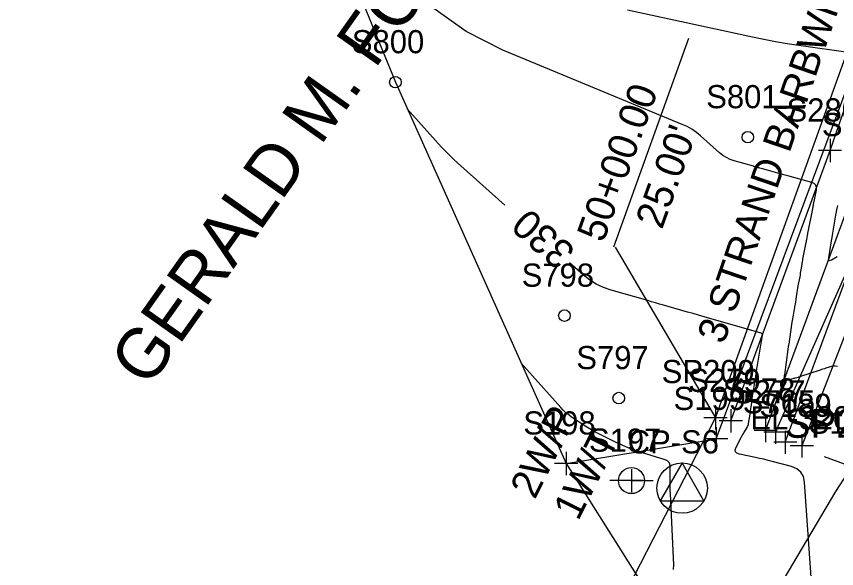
# Model space of a CAD drawing. Extents: x 816928 to 825690, y 436959 to 448212.
# Drawn here: x 818545.2 to 818686.8, y 444502.7 to 444598.1 of the extents above; entities that cross this region are included whole.
import ezdxf

# ---------------------------------------------------------------- set-up
doc = ezdxf.new("R2010")
doc.units = 0
for name, color, linetype in [('DESIGN - SCRATCH - User 1', 7, 'Continuous'), ('SURVEY - CENTERLINE - Preliminary - Development', 7, 'Continuous'), ('SURVEY - CENTERLINE - Preliminary Text', 7, 'Continuous'), ('SURVEY - CONTOURS - Index with Text', 7, 'Continuous'), ('SURVEY - CONTOURS - Intermediate with optional Text', 7, 'Continuous'), ('SURVEY - CONTROL with Text', 7, 'Continuous'), ('SURVEY - DRAINAGE - Area Shapes', 7, 'Continuous'), ('SURVEY - DTM - Breaklines', 7, 'Continuous'), ('SURVEY - DTM - Breaklines - Points - Locators', 7, 'Continuous'), ('SURVEY - DTM - Breaklines - Points - Numbers', 7, 'Continuous'), ('SURVEY - DTM - Spot Points - Locators', 7, 'Continuous'), ('SURVEY - DTM - Spot Points - Point Numbers', 7, 'Continuous'), ('SURVEY - NON-TRANSPORTATION - Features', 7, 'Continuous'), ('SURVEY - NON-TRANSPORTATION - Features - Points - Locators', 7, 'Continuous'), ('SURVEY - NON-TRANSPORTATION - Features - Points - Numbers', 7, 'Continuous'), ('SURVEY - NON-TRANSPORTATION - Features Text', 7, 'Continuous'), ('SURVEY - PROPERTY - Owners', 7, 'Continuous'), ('SURVEY - PROPERTY - Parcels', 7, 'Continuous'), ('SURVEY - PROPERTY - ROW Lines', 7, 'Continuous'), ('SURVEY - PROPERTY - ROW Lines - Points - Elevations', 7, 'Continuous'), ('SURVEY - PROPERTY - ROW Lines - Points - Locators', 7, 'Continuous'), ('SURVEY - PROPERTY - ROW Lines - Points - Numbers', 7, 'Continuous'), ('SURVEY - PROPERTY - Station and Offset Flags', 7, 'Continuous'), ('SURVEY - TRANSPORTATION - Roads', 7, 'Continuous'), ('SURVEY - TRANSPORTATION - Roads - Points - Locators', 7, 'Continuous'), ('SURVEY - TRANSPORTATION - Roads - Points - Numbers', 7, 'Continuous'), ('SURVEY - UTILITIES - Gas - Points - Locators', 7, 'Continuous'), ('SURVEY - UTILITIES - Gas - Points - Numbers', 7, 'Continuous'), ('SURVEY - UTILITIES - Gas with Text', 7, 'Continuous'), ('SURVEY - UTILITIES - Poles and Miscellaneous - Points - Locators', 7, 'Continuous'), ('SURVEY - UTILITIES - Poles and Miscellaneous - Points - Numbers', 7, 'Continuous'), ('SURVEY - UTILITIES - Poles and Miscellaneous with Text', 7, 'Continuous')]:
    doc.layers.add(name, color=color, linetype=linetype)

msp = doc.modelspace()

# ---------------------------------------------------------------- linework, layer by layer
at = {"layer": 'DESIGN - SCRATCH - User 1'}
msp.add_lwpolyline([(818705.72, 444876.51), (818677.89, 444822.37), (818647.85, 444766.47), (818627.5, 444720.97), (818604.18, 444676.53), (818583.87, 444652.29), (818610.67, 444586.77), (818640.15, 444520.89), (818676.04, 444463.99)], dxfattribs=at)
at = {"layer": 'SURVEY - CENTERLINE - Preliminary Text'}
msp.add_line((818689.48, 444520.32), (818684.77, 444522.01), dxfattribs=at)
at = {"layer": 'SURVEY - CONTOURS - Index with Text'}
for points in [[(818629.55, 444565.54), (818621.98, 444572.29), (818620.82, 444573.35), (818619.71, 444574.44), (818618.62, 444575.56), (818617.57, 444576.71), (818612.72, 444582.17)], [(818682.87, 444495.45), (818681.3, 444517.68), (818681.11, 444518.65), (818680.68, 444519.41), (818680, 444519.98), (818679.09, 444520.35), (818675.73, 444521.24), (818675.01, 444521.42), (818674.28, 444521.6), (818673.55, 444521.76), (818672.83, 444521.92), (818670.06, 444522.5), (818669.62, 444522.66), (818669.39, 444522.9), (818669.35, 444523.25), (818669.5, 444523.68), (818670.44, 444525.46), (818670.56, 444525.69), (818670.69, 444525.92), (818670.82, 444526.15), (818670.96, 444526.37), (818671.4, 444527.11), (818671.49, 444527.27), (818671.56, 444527.43), (818671.61, 444527.61), (818671.65, 444527.79), (818671.96, 444529.74), (818672.01, 444530.04), (818672.05, 444530.35), (818672.09, 444530.65), (818672.13, 444530.96), (818672.25, 444531.95), (818672.28, 444532.17), (818672.3, 444532.38), (818672.34, 444532.59), (818672.37, 444532.8), (818672.89, 444535.94), (818672.92, 444536.1), (818672.94, 444536.26), (818672.96, 444536.42), (818672.98, 444536.58), (818673.05, 444537.1), (818673.06, 444537.21), (818673.08, 444537.32), (818673.1, 444537.43), (818673.12, 444537.54), (818673.89, 444542.01), (818673.89, 444542.04), (818673.9, 444542.07), (818673.9, 444542.09), (818673.91, 444542.12), (818673.92, 444542.21), (818673.92, 444542.23), (818673.92, 444542.24), (818673.93, 444542.26), (818673.93, 444542.28), (818674.06, 444542.99), (818674.06, 444543.13), (818674.02, 444543.24), (818673.94, 444543.33), (818673.81, 444543.38), (818664, 444546.21), (818663.03, 444546.49), (818662.06, 444546.77), (818661.09, 444547.05), (818660.12, 444547.33), (818656.95, 444548.24), (818656.27, 444548.44), (818655.59, 444548.64), (818654.91, 444548.83), (818654.23, 444549.02), (818647.9, 444550.84), (818646.58, 444551.29), (818645.33, 444551.89), (818644.17, 444552.62), (818643.07, 444553.49), (818640.75, 444555.56)]]:
    msp.add_lwpolyline(points, dxfattribs=at)
at = {"layer": 'SURVEY - CONTOURS - Intermediate with optional Text'}
for points in [[(818687.03, 444537.65), (818686.61, 444537.69), (818686.56, 444537.7), (818686.52, 444537.7), (818686.47, 444537.71), (818686.42, 444537.71), (818686.27, 444537.73), (818686.24, 444537.73), (818686.21, 444537.73), (818686.18, 444537.73), (818686.15, 444537.72), (818684.99, 444537.34), (818684.74, 444537.26), (818684.49, 444537.18), (818684.24, 444537.1), (818683.99, 444537.01), (818680.64, 444535.91), (818680.6, 444535.89), (818680.56, 444535.88), (818680.52, 444535.86), (818680.48, 444535.85), (818680.35, 444535.79), (818680.33, 444535.78), (818680.3, 444535.77), (818680.27, 444535.77), (818680.24, 444535.76), (818679.73, 444535.64), (818679.62, 444535.61), (818679.52, 444535.58), (818679.41, 444535.55), (818679.3, 444535.52), (818678.17, 444535.21), (818678.13, 444535.19), (818678.08, 444535.19), (818678.03, 444535.18), (818677.98, 444535.17), (818677.82, 444535.17), (818677.79, 444535.17), (818677.77, 444535.18), (818677.76, 444535.2), (818677.76, 444535.23), (818677.85, 444535.94), (818677.85, 444535.96), (818677.86, 444535.99), (818677.86, 444536.02), (818677.87, 444536.04), (818677.88, 444536.13), (818677.88, 444536.14), (818677.89, 444536.16), (818677.89, 444536.18), (818677.89, 444536.2), (818678.49, 444540.6), (818678.51, 444540.78), (818678.54, 444540.95), (818678.57, 444541.13), (818678.6, 444541.3), (818678.7, 444541.87), (818678.72, 444541.99), (818678.74, 444542.11), (818678.76, 444542.24), (818678.78, 444542.36), (818679.19, 444545.28), (818679.24, 444545.59), (818679.29, 444545.9), (818679.34, 444546.21), (818679.4, 444546.52), (818679.59, 444547.53), (818679.63, 444547.75), (818679.66, 444547.97), (818679.7, 444548.19), (818679.73, 444548.41), (818679.99, 444550.11), (818680.04, 444550.47), (818680.1, 444550.83), (818680.17, 444551.2), (818680.23, 444551.56), (818680.53, 444553.14), (818680.59, 444553.44), (818680.64, 444553.74), (818680.69, 444554.04), (818680.74, 444554.34), (818680.9, 444555.33), (818680.93, 444555.54), (818680.97, 444555.75), (818681, 444555.96), (818681.04, 444556.17), (818681.61, 444559.06), (818681.65, 444559.25), (818681.68, 444559.43), (818681.71, 444559.61), (818681.74, 444559.8), (818681.84, 444560.4), (818681.86, 444560.53), (818681.88, 444560.66), (818681.91, 444560.79), (818681.93, 444560.92), (818682.73, 444564.9), (818682.75, 444564.98), (818682.76, 444565.05), (818682.78, 444565.13), (818682.79, 444565.2), (818682.83, 444565.45), (818682.84, 444565.5), (818682.85, 444565.56), (818682.86, 444565.61), (818682.87, 444565.66), (818683.37, 444568.1), (818683.4, 444568.57), (818683.27, 444568.95), (818682.99, 444569.24), (818682.56, 444569.43), (818678.4, 444570.59), (818677.97, 444570.71), (818677.54, 444570.83), (818677.11, 444570.95), (818676.68, 444571.07), (818675.07, 444571.52), (818674.87, 444571.57), (818674.68, 444571.63), (818674.48, 444571.68), (818674.29, 444571.73), (818673.6, 444571.93), (818673.49, 444571.96), (818673.38, 444571.99), (818673.27, 444572.02), (818673.16, 444572.05), (818672.8, 444572.15), (818672.72, 444572.17), (818672.64, 444572.19), (818672.57, 444572.22), (818672.49, 444572.24), (818669.17, 444573.19), (818668.48, 444573.43), (818667.83, 444573.74), (818667.22, 444574.12), (818666.65, 444574.58), (818663.36, 444577.51), (818662.64, 444578.1), (818661.87, 444578.63), (818661.06, 444579.09), (818660.21, 444579.48), (818629.22, 444592.33), (818622.92, 444595.5), (818617.31, 444599.48)], [(818650.72, 444599.3), (818672.3, 444594.61), (818674.29, 444594.19), (818676.29, 444593.81), (818678.3, 444593.47), (818680.32, 444593.16), (818689.22, 444591.87)], [(818686.99, 444565.44), (818686.85, 444564.73), (818686.81, 444564.58), (818686.79, 444564.43), (818686.76, 444564.27), (818686.73, 444564.12), (818686.1, 444560.35), (818686.08, 444560.25), (818686.06, 444560.15), (818686.05, 444560.06), (818686.03, 444559.96), (818685.96, 444559.64), (818685.95, 444559.57), (818685.94, 444559.5), (818685.92, 444559.43), (818685.91, 444559.37), (818685.44, 444556.43), (818685.43, 444556.14), (818685.51, 444555.99), (818685.68, 444555.97), (818685.94, 444556.08), (818686.95, 444556.66)], [(818658.71, 444502.58), (818658.76, 444503.38), (818658.16, 444515.64), (818658.14, 444516.29), (818658.12, 444516.93), (818658.11, 444517.57), (818658.11, 444518.22), (818658.13, 444520.32), (818658.08, 444520.74), (818657.92, 444521.07), (818657.65, 444521.32), (818657.27, 444521.5), (818652.44, 444523.03), (818651.51, 444523.34), (818650.59, 444523.69), (818649.69, 444524.08), (818648.8, 444524.5), (818645.93, 444525.93), (818645.32, 444526.25), (818644.72, 444526.58), (818644.13, 444526.93), (818643.55, 444527.3), (818641.1, 444528.9), (818640.59, 444529.26), (818640.1, 444529.65), (818639.65, 444530.07), (818639.22, 444530.53), (818632.39, 444538.23)]]:
    msp.add_lwpolyline(points, dxfattribs=at)
at = {"layer": 'SURVEY - CONTROL with Text'}
for p, q in [((818660.18, 444520.97), (818656.41, 444514.45)), ((818663.94, 444514.45), (818660.18, 444520.97)), ((818660.18, 444516.62), (818660.18, 444516.62)), ((818656.41, 444514.45), (818663.94, 444514.45))]:
    msp.add_line(p, q, dxfattribs=at)
msp.add_circle((818660.18, 444516.62), 4.35, dxfattribs=at)
at = {"layer": 'SURVEY - DRAINAGE - Area Shapes'}
msp.add_line((818686.72, 444516.06), (818689.48, 444520.32), dxfattribs=at)
msp.add_lwpolyline([(817903.8, 442541.98), (818070.27, 442887.73), (818031.86, 443297.51), (818262.36, 443809.74), (818428.83, 443989.01), (818556.89, 444296.35), (818686.72, 444516.06)], dxfattribs=at)
at = {"layer": 'SURVEY - DTM - Breaklines'}
for points in [[(818668.59, 444528.25), (818685.72, 444574.97), (818701.79, 444621.45), (818719.06, 444668.19), (818736.24, 444715.25), (818753.95, 444762.85), (818774.46, 444810.97), (818792.45, 444864.45), (818805.63, 444902.92), (818824.67, 444952.98), (818842.7, 444999.99), (818860.04, 445043.66), (818874.78, 445092.7), (818880.83, 445100.46), (818882.71, 445127.32), (818888.7, 445139.72), (818911.77, 445177.18)], [(818674.6, 444526.59), (818691.48, 444572.45), (818707.88, 444620.16), (818723.91, 444667.23), (818740.64, 444713.78), (818759.18, 444760.75), (818780.01, 444808.95), (818796, 444863.51), (818810.8, 444901.84), (818829.91, 444950.6), (818849.2, 444995.99), (818867.15, 445042.08), (818885.66, 445087.7), (818887.91, 445097.82), (818891.19, 445123.69), (818896.18, 445136.06), (818917.38, 445175.79)], [(818676.31, 444526.27), (818695.98, 444570.72), (818712.39, 444618.98), (818728.83, 444665.29), (818745.89, 444712.28), (818764.81, 444759.05), (818784.52, 444806.67), (818801.14, 444861.81), (818818.98, 444900.09), (818838.24, 444946.22), (818855.87, 444992.17), (818873.7, 445038.58), (818892.29, 445085.58), (818894.59, 445096.56), (818896.48, 445123.31), (818901.19, 445133.75), (818919.53, 445174.23), (818947.17, 445168.06)]]:
    msp.add_lwpolyline(points, dxfattribs=at)
at = {"layer": 'SURVEY - DTM - Breaklines - Points - Locators'}
for p, q in [((818685.72, 444576.97), (818685.72, 444572.97)), ((818687.72, 444574.97), (818683.72, 444574.97)), ((818668.59, 444530.25), (818668.59, 444526.25)), ((818670.59, 444528.25), (818666.59, 444528.25)), ((818674.6, 444528.59), (818674.6, 444524.59)), ((818676.31, 444528.27), (818676.31, 444524.27)), ((818676.6, 444526.59), (818672.6, 444526.59)), ((818678.31, 444526.27), (818674.31, 444526.27))]:
    msp.add_line(p, q, dxfattribs=at)
at = {"layer": 'SURVEY - DTM - Spot Points - Locators'}
for centre in [(818610.67, 444586.77), (818671.52, 444577.27), (818639.86, 444546.43), (818649.24, 444532.18)]:
    msp.add_circle(centre, 1, dxfattribs=at)
at = {"layer": 'SURVEY - NON-TRANSPORTATION - Features'}
msp.add_lwpolyline([(818640.15, 444520.89), (818666.05, 444525.13), (818695.51, 444604.3), (818745.61, 444742.32), (818768.23, 444804.49), (818806.14, 444902.96), (818848.51, 445015.37), (818878.72, 445102.03)], dxfattribs=at)
at = {"layer": 'SURVEY - NON-TRANSPORTATION - Features - Points - Locators'}
for p, q in [((818666.05, 444527.13), (818666.05, 444523.13)), ((818668.05, 444525.13), (818664.05, 444525.13)), ((818640.15, 444522.89), (818640.15, 444518.89)), ((818642.15, 444520.89), (818638.15, 444520.89))]:
    msp.add_line(p, q, dxfattribs=at)
at = {"layer": 'SURVEY - PROPERTY - Parcels'}
for p, q in [((818665.95, 444528.77), (818717.18, 444671.42)), ((818570.54, 444343.53), (818665.95, 444528.77))]:
    msp.add_line(p, q, dxfattribs=at)
at = {"layer": 'SURVEY - PROPERTY - ROW Lines'}
for p, q in [((818665.95, 444528.77), (818717.18, 444671.42)), ((818570.54, 444343.53), (818665.95, 444528.77))]:
    msp.add_line(p, q, dxfattribs=at)
at = {"layer": 'SURVEY - PROPERTY - ROW Lines - Points - Locators'}
for p, q in [((818665.95, 444530.77), (818665.95, 444526.77)), ((818667.95, 444528.77), (818663.95, 444528.77))]:
    msp.add_line(p, q, dxfattribs=at)
at = {"layer": 'SURVEY - PROPERTY - Station and Offset Flags'}
msp.add_line((818661.29, 444594.3), (818648.35, 444558.26), dxfattribs=at)
msp.add_lwpolyline([(818648.6, 444558.26), (818665.95, 444528.77)], dxfattribs=at)
at = {"layer": 'SURVEY - TRANSPORTATION - Roads'}
msp.add_lwpolyline([(818965.23, 445155.36), (818951.41, 445165.35), (818926.02, 445127.5), (818900.33, 445082.5), (818878.31, 445036.45), (818858.82, 444990.15), (818840.56, 444944.19), (818822.72, 444897.89), (818804.42, 444851.44), (818785.95, 444804.73), (818767.42, 444758.09), (818749.48, 444712.19), (818731.94, 444664.32), (818715.46, 444617.82), (818698.91, 444570.49), (818680.86, 444523.94)], dxfattribs=at)
at = {"layer": 'SURVEY - TRANSPORTATION - Roads - Points - Locators'}
for p, q in [((818680.86, 444525.94), (818680.86, 444521.94)), ((818682.86, 444523.94), (818678.86, 444523.94))]:
    msp.add_line(p, q, dxfattribs=at)
at = {"layer": 'SURVEY - UTILITIES - Gas - Points - Locators'}
for p, q in [((818677.99, 444526.55), (818677.99, 444522.55)), ((818679.99, 444524.55), (818675.99, 444524.55))]:
    msp.add_line(p, q, dxfattribs=at)
at = {"layer": 'SURVEY - UTILITIES - Gas with Text'}
msp.add_lwpolyline([(818677.99, 444524.55), (818704.19, 444595.26), (818729, 444664.07), (818764.63, 444758.42), (818803.58, 444855.27), (818837.4, 444944.84), (818872.36, 445029.49), (818905.91, 445098), (818946.07, 445164.69)], dxfattribs=at)
at = {"layer": 'SURVEY - UTILITIES - Poles and Miscellaneous - Points - Locators'}
for p, q in [((818651.44, 444519.92), (818651.44, 444515.92)), ((818653.44, 444517.92), (818649.44, 444517.92))]:
    msp.add_line(p, q, dxfattribs=at)
at = {"layer": 'SURVEY - UTILITIES - Poles and Miscellaneous with Text'}
for q in [(818647.69, 444517.92), (818655.19, 444517.92)]:
    msp.add_line((818651.44, 444517.92), q, dxfattribs=at)
msp.add_circle((818651.44, 444517.92), 2.25, dxfattribs=at)

# ---------------------------------------------------------------- texts
at = {"layer": 'SURVEY - CENTERLINE - Preliminary - Development'}
msp.add_text('SP204', height=5, dxfattribs=at).set_placement((818677.87, 444525.32))
at = {"layer": 'SURVEY - CONTOURS - Index with Text'}
msp.add_text('330', height=5, rotation=138.3011, dxfattribs=at).set_placement((818642, 444557.8))
at = {"layer": 'SURVEY - CONTROL with Text'}
msp.add_text('CP-S6', height=4, dxfattribs=at).set_placement((818650.78, 444522.62))
at = {"layer": 'SURVEY - DTM - Breaklines - Points - Numbers'}
for s, p in [('S280', (818678.21, 444579.97)), ('S281', (818684.3, 444577.45)), ('S279', (818661.24, 444533.25)), ('S278', (818667.21, 444531.59)), ('S277', (818668.97, 444531.27)), ('S191', (818682.02, 444526.03))]:
    msp.add_text(s, height=4, dxfattribs=at).set_placement(p)
at = {"layer": 'SURVEY - DTM - Spot Points - Point Numbers'}
for s, p in [('S800', (818603.16, 444591.77)), ('S801', (818664.34, 444582.27)), ('S798', (818632.48, 444551.43)), ('S797', (818641.91, 444537.18))]:
    msp.add_text(s, height=4, dxfattribs=at).set_placement(p)
at = {"layer": 'SURVEY - NON-TRANSPORTATION - Features - Points - Numbers'}
for s, p in [('S199', (818658.7, 444530.13)), ('S198', (818632.76, 444525.89))]:
    msp.add_text(s, height=4, dxfattribs=at).set_placement(p)
at = {"layer": 'SURVEY - NON-TRANSPORTATION - Features Text'}
msp.add_text('3 STRAND BARBWIRE', height=5, rotation=71.1188, dxfattribs=at).set_placement((818667.39, 444541.34))
at = {"layer": 'SURVEY - PROPERTY - Owners'}
msp.add_text('GERALD M. FORBESS', height=8.75, rotation=54.6815, dxfattribs=at).set_placement((818568.04, 444533.74))
at = {"layer": 'SURVEY - PROPERTY - ROW Lines - Points - Elevations'}
msp.add_text('EL-320.00', height=4, dxfattribs=at).set_placement((818671.95, 444526.77))
at = {"layer": 'SURVEY - PROPERTY - ROW Lines - Points - Numbers'}
msp.add_text('SP209', height=4, dxfattribs=at).set_placement((818656.65, 444534.77))
at = {"layer": 'SURVEY - PROPERTY - Station and Offset Flags'}
for s, p in [('50+00.00', (818646.58, 444558.89)), ("25.00'", (818656.7, 444561.18))]:
    msp.add_text(s, height=5, rotation=70.2462, dxfattribs=at).set_placement(p)
at = {"layer": 'SURVEY - TRANSPORTATION - Roads - Points - Numbers'}
msp.add_text('S189', height=4, dxfattribs=at).set_placement((818673.51, 444528.94))
at = {"layer": 'SURVEY - UTILITIES - Gas - Points - Numbers'}
msp.add_text('S765', height=4, dxfattribs=at).set_placement((818670.65, 444529.55))
at = {"layer": 'SURVEY - UTILITIES - Poles and Miscellaneous - Points - Numbers'}
msp.add_text('S197', height=4, dxfattribs=at).set_placement((818644.1, 444522.92))
at = {"layer": 'SURVEY - UTILITIES - Poles and Miscellaneous with Text'}
for s, p in [('2W/P', (818634.75, 444514.54)), ('1W/T', (818642.21, 444510.82))]:
    msp.add_text(s, height=5, rotation=63.4349, dxfattribs=at).set_placement(p)

doc.saveas('drawing.dxf')
